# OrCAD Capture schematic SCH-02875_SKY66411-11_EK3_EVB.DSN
size B; title: SKY66411-11 (CSP) EK3 EVB; rev: D1; company: SKYWORKS SOLUTIONS, INC.; note: SCH-02875; note: OTTAWA, ONTARIO CANADA
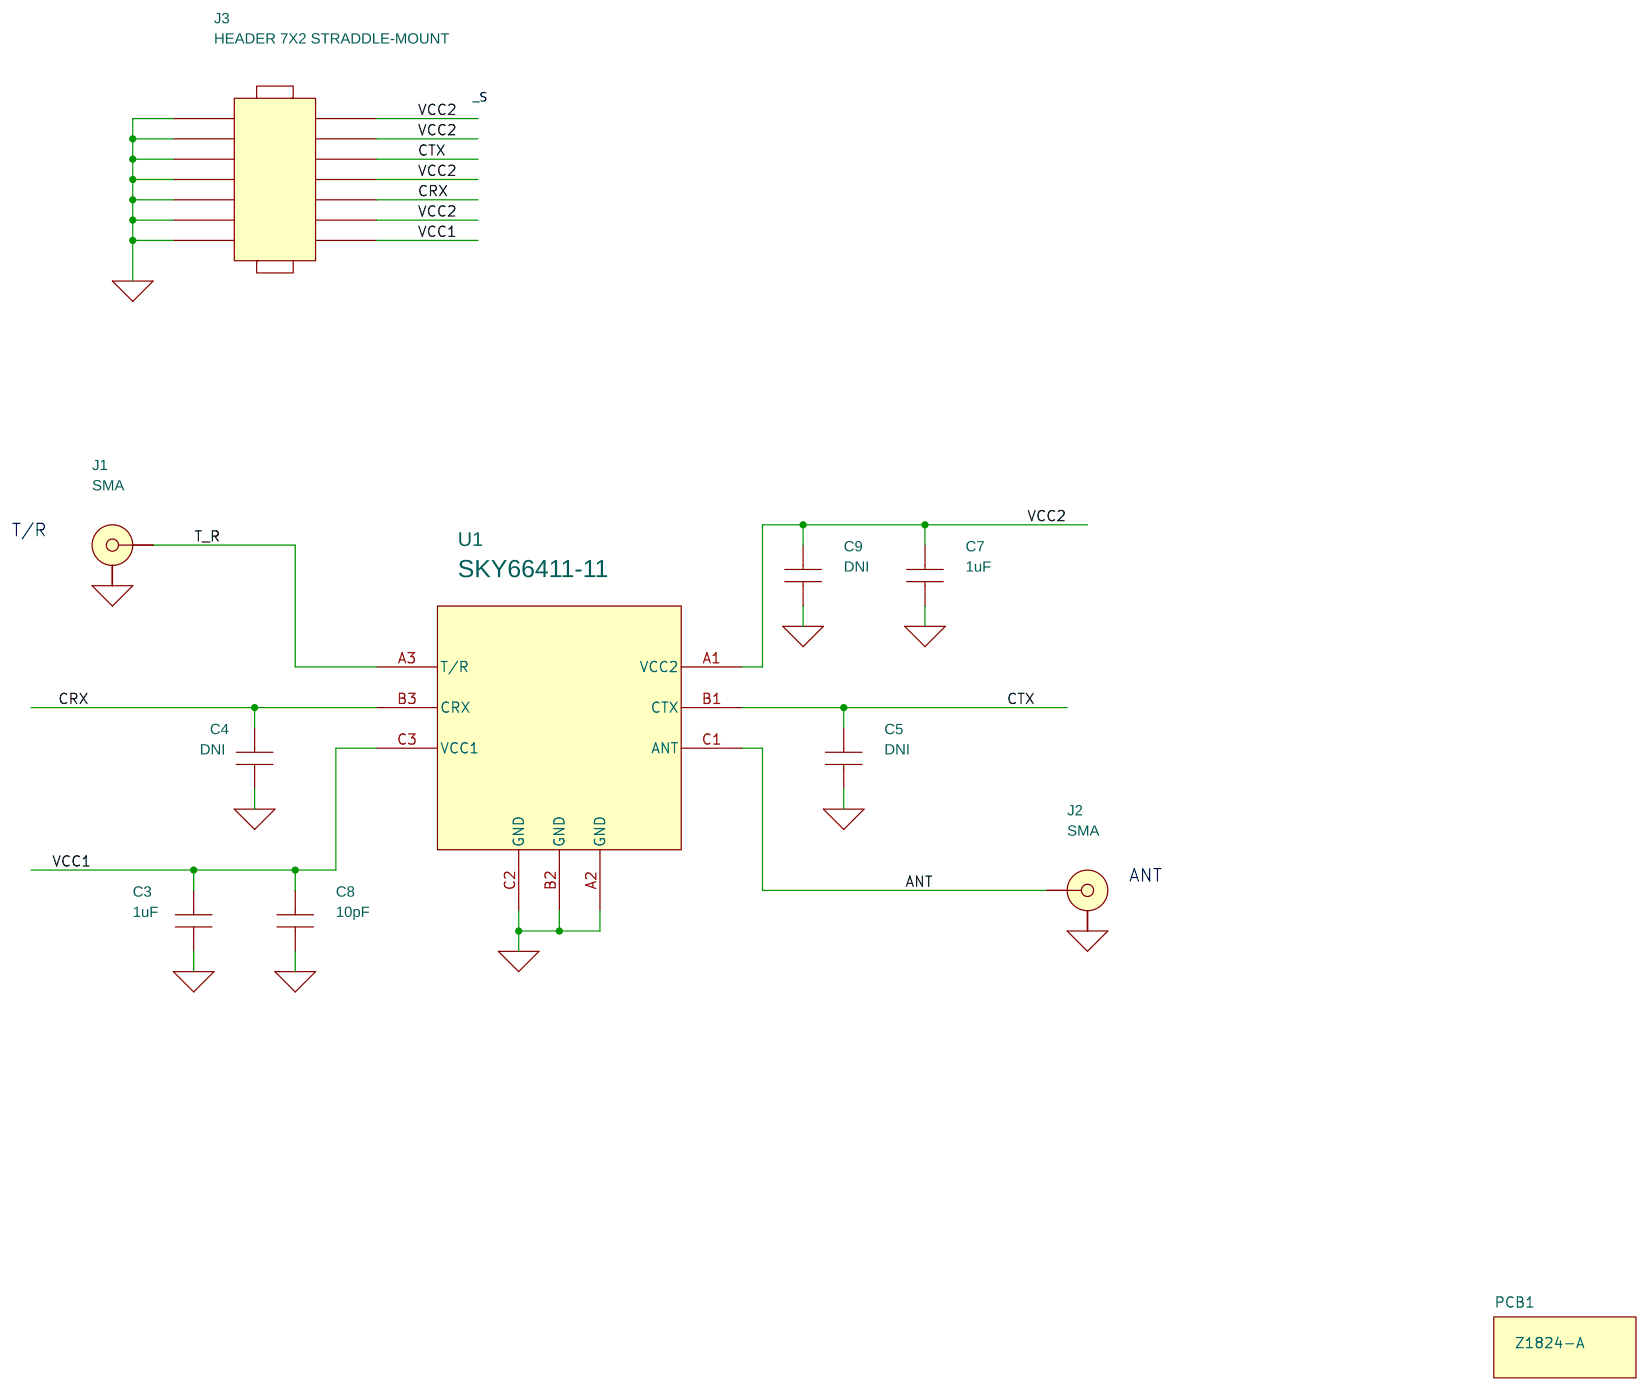
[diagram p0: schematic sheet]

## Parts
C3  1uF  [SMDC1000X500]
C4  DNI  [SMDC1000X500]
C5  DNI  [SMDC1000X500]
C7  1uF  [SMDC1000X500]
C8  10pF  [SMDC600X300]
C9  DNI  [SMDC600X300]
J1  SMA  [SMA_END_E]
J2  SMA  [SMA_END_E]
J3  HEADER 7X2 STRADDLE-MOUNT  [TSW-107-07-G-D_edge]
PCB1  Z1824-A
U1  SKY66411-11

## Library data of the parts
C3 C7 = C: CAP CER 1UF 10V X7S 0402; Manufacturer: Murata Electronics; Manufacturer_PN: GCM155C71A105KE38D; Material_Type: X7S; PACKAGE: 0402; Ratings: AEC-Q200; Size / Dimension: 0.039" L x 0.020" W (1.00mm x 0.50mm); Temperature_Range: -55°C ~ 125°C; Thickness (Max): 0.022" (0.55mm); Tolerance: ±10%; Voltage: 10V
C4 C5 = C: PACKAGE: 0402; Ratings: NONE
C8 = C: CAP CER 10PF 25V C0G/NP0 0201; Manufacturer: Murata Electronics; Manufacturer_PN: GRM0335C1E100JD01; Material_Type: C0G, NP0; PACKAGE: 0201; Ratings: NONE; Size / Dimension: 0.024" L x 0.012" W (0.60mm x 0.30mm); Temperature_Range: -55°C ~ 125°C; Thickness (Max): 0.013" (0.33mm); Tolerance: ±5%; Voltage: 25V
C9 = C: PACKAGE: 0201; Ratings: NONE
J1 J2 = RF_3pin: SMA End Launch Straight Jack Receptacle - Tab Contact; Contact Type: Female; Manufacturer: Multicomp/SPC; Manufacturer_PN: 615R54-021 (R19-070-18-0032210MM); Number of Positions: 1; Number of Rows: 1; PACKAGE: SMA_END
J3 = HEADER_7X2: CONN HEADER VERT 14POS (7X2) 2.54MM; Contact Length - Mating: 0.230" (5.84mm); Contact Type: Male Pin; Manufacturer: Samtec Inc.; Manufacturer_PN: TSW-107-07-G-D; Number of Positions: 14; Number of Rows: 2; PACKAGE: 0.100" (2.54mm); Shrouding: Unshrouded
PCB1 = PCB: Manufacturer: Skyworks
U1 = SKY66411-11: 2.4 GHz Front-End Module for Bluetooth®/Zigbee®/Thread Applications; Manufacturer: Skyworks

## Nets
GND: C3.2 C4.2 C5.2 C7.2 C8.2 C9.2 J1.2(GND) J1.3(GND) J2.2(GND) J2.3(GND) J3.2 J3.4 J3.6 J3.8 J3.10 J3.12 J3.14 U1.A2(GND) U1.B2(GND) U1.C2(GND)
VCC1: C3.1 C8.1 J3.13 U1.C3(VCC1)
VCC2: C7.1 C9.1 J3.1 J3.3 J3.7 J3.11 U1.A1(VCC2)
ANT: J2.1(SIG) U1.C1(ANT)
CRX: C4.1 J3.9 U1.B3(CRX)
CTX: C5.1 J3.5 U1.B1(CTX)
T_R: J1.1(SIG) U1.A3(T/R)

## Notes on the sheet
- _S
- T/R
- ANT
